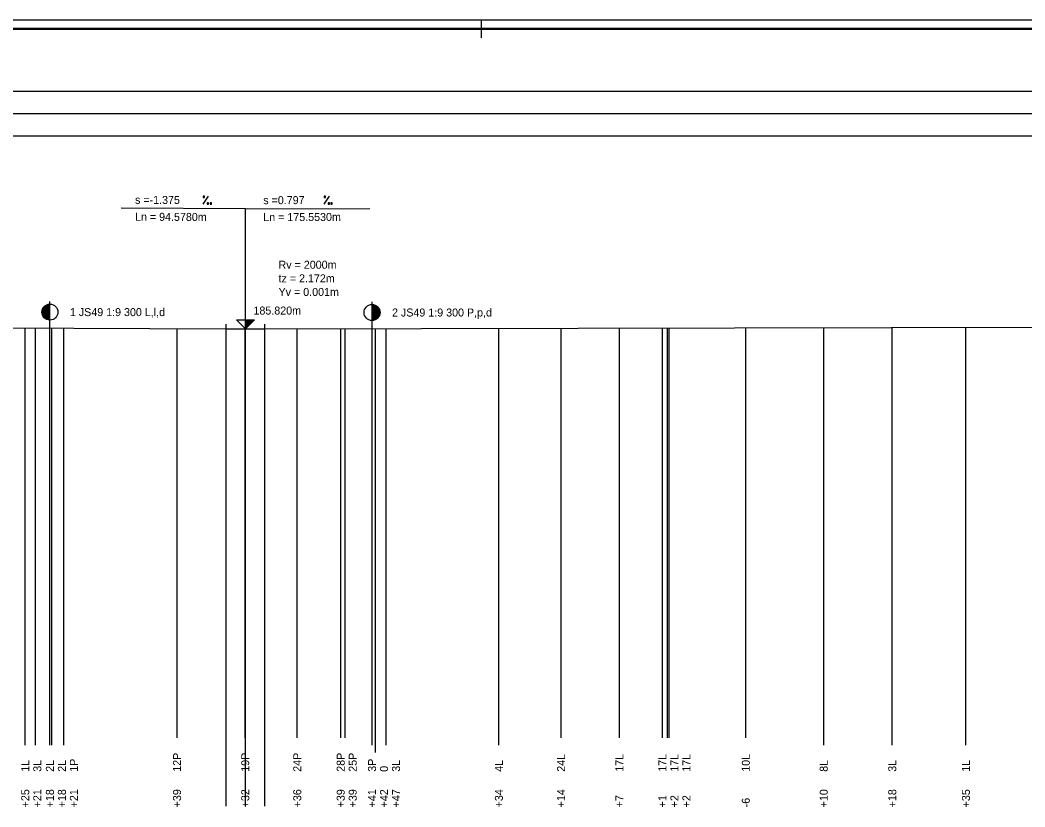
# Model space of a CAD drawing. Extents: x 0 to 10087, y -805 to 297.
# Drawn here: x 7666.2 to 7892.2, y 120.1 to 297 of the extents above; entities that cross this region are included whole.
import ezdxf

# ---------------------------------------------------------------- set-up
doc = ezdxf.new("R2010")
doc.units = 0
for name, color, linetype in [('CARA_S_OBJEKTY', 7, 'Continuous'), ('CARKY_HODNOT', 7, 'Continuous'), ('NIVELETA_CARA', 7, 'Continuous'), ('NIVELETA_TEXT', 7, 'Continuous'), ('OBJEKTY_TEXT', 7, 'Continuous'), ('RAM', 7, 'Continuous'), ('TEXT', 7, 'Continuous')]:
    doc.layers.add(name, color=color, linetype=linetype)

msp = doc.modelspace()

# ---------------------------------------------------------------- linework, layer by layer
at = {"layer": 'CARKY_HODNOT'}
for p, q in [((7667.33, 138.35), (7667.33, 227.77)), ((7669.61, 138.35), (7669.61, 227.76)), ((7672.87, 138.35), (7672.87, 227.75)), ((7673.27, 138.35), (7673.27, 227.75)), ((7676.04, 138.35), (7676.04, 227.74)), ((7701.47, 138.35), (7701.47, 227.65)), ((7712.52, 138.35), (7712.52, 227.61)), ((7716.82, 138.35), (7716.82, 227.61)), ((7716.87, 138.35), (7716.87, 227.61)), ((7721.21, 138.35), (7721.21, 227.61)), ((7728.52, 138.35), (7728.52, 227.62)), ((7738.3, 138.35), (7738.3, 227.64)), ((7739.33, 138.35), (7739.33, 227.64)), ((7745.34, 138.35), (7745.34, 227.66)), ((7746.1, 138.35), (7746.1, 227.66)), ((7748.5, 138.35), (7748.5, 227.66)), ((7773.88, 138.35), (7773.88, 227.71)), ((7787.88, 138.35), (7787.88, 227.74)), ((7801.01, 138.35), (7801.01, 227.77)), ((7810.68, 138.35), (7810.68, 227.79)), ((7811.8, 138.35), (7811.8, 227.79)), ((7812.16, 138.35), (7812.16, 227.79)), ((7829.44, 138.35), (7829.44, 227.82)), ((7846.97, 138.35), (7846.97, 227.86)), ((7862.39, 138.35), (7862.39, 227.89)), ((7878.97, 138.35), (7878.97, 227.92)), ((7667.33, 134), (7667.33, 138.35)), ((7669.61, 134), (7669.61, 138.35)), ((7672.87, 134), (7672.87, 138.35)), ((7673.27, 134), (7673.27, 138.35)), ((7676.04, 134), (7676.04, 138.35)), ((7701.47, 135.65), (7701.47, 138.35)), ((7712.52, 126.2), (7712.52, 138.35)), ((7716.82, 135.65), (7716.82, 138.35)), ((7716.87, 126.2), (7716.87, 138.35)), ((7721.21, 126.2), (7721.21, 138.35)), ((7728.52, 135.65), (7728.52, 138.35)), ((7738.3, 135.65), (7738.3, 138.35)), ((7739.33, 135.65), (7739.33, 138.35)), ((7745.34, 134), (7745.34, 138.35)), ((7746.1, 132.35), (7746.1, 138.35)), ((7748.5, 134), (7748.5, 138.35)), ((7773.88, 134), (7773.88, 138.35)), ((7787.88, 135.65), (7787.88, 138.35)), ((7801.01, 135.65), (7801.01, 138.35)), ((7810.68, 135.65), (7810.68, 138.35)), ((7811.8, 135.65), (7811.8, 138.35)), ((7812.16, 135.65), (7812.16, 138.35)), ((7829.44, 135.65), (7829.44, 138.35)), ((7846.97, 134), (7846.97, 138.35)), ((7862.39, 134), (7862.39, 138.35)), ((7878.97, 134), (7878.97, 138.35)), ((7712.52, 120.25), (7712.52, 126.2)), ((7716.87, 120.25), (7716.87, 126.2)), ((7721.21, 120.25), (7721.21, 126.2))]:
    msp.add_line(p, q, dxfattribs=at)
at = {"layer": 'NIVELETA_CARA'}
for p, q in [((300, 281), (8321.33, 281)), ((300, 276), (8321.33, 276)), ((300, 271), (8321.33, 271)), ((7716.87, 254.6), (7688.87, 254.7)), ((7716.87, 254.6), (7744.87, 254.66)), ((7716.87, 227.6), (7716.87, 254.6)), ((7712.52, 227.61), (7712.52, 228.61)), ((7716.87, 227.6), (7714.87, 229.6)), ((7714.87, 229.6), (7718.87, 229.6)), ((7716.87, 227.6), (7716.87, 229.6)), ((7718.87, 229.6), (7716.87, 227.6)), ((7716.93, 227.67), (7716.93, 229.6)), ((7717, 227.73), (7717, 229.6)), ((7717.07, 227.8), (7717.07, 229.6)), ((7717.13, 227.87), (7717.13, 229.6)), ((7717.2, 227.93), (7717.2, 229.6)), ((7717.27, 228), (7717.27, 229.6)), ((7717.33, 228.07), (7717.33, 229.6)), ((7717.4, 228.13), (7717.4, 229.6)), ((7717.47, 228.2), (7717.47, 229.6)), ((7717.53, 228.27), (7717.53, 229.6)), ((7717.6, 228.33), (7717.6, 229.6)), ((7717.67, 228.4), (7717.67, 229.6)), ((7717.73, 228.47), (7717.73, 229.6)), ((7717.8, 228.53), (7717.8, 229.6)), ((7717.87, 228.6), (7717.87, 229.6)), ((7717.93, 228.67), (7717.93, 229.6)), ((7718, 228.73), (7718, 229.6)), ((7718.07, 228.8), (7718.07, 229.6)), ((7718.13, 228.87), (7718.13, 229.6)), ((7718.2, 228.93), (7718.2, 229.6)), ((7718.27, 229), (7718.27, 229.6)), ((7718.33, 229.07), (7718.33, 229.6)), ((7718.4, 229.13), (7718.4, 229.6)), ((7718.47, 229.2), (7718.47, 229.6)), ((7718.53, 229.27), (7718.53, 229.6)), ((7718.6, 229.33), (7718.6, 229.6)), ((7718.67, 229.4), (7718.67, 229.6)), ((7718.73, 229.47), (7718.73, 229.6)), ((7718.8, 229.53), (7718.8, 229.6)), ((7721.21, 227.61), (7721.21, 228.61)), ((7532.94, 228.23), (7712.52, 227.61)), ((7712.52, 227.61), (7716.87, 227.6)), ((7712.52, 227.61), (7713.02, 227.61)), ((7713.02, 227.61), (7713.52, 227.61)), ((7713.52, 227.61), (7714.02, 227.61)), ((7714.02, 227.61), (7714.07, 227.61)), ((7716.87, 227.6), (7721.21, 227.61)), ((7719.67, 227.61), (7720.17, 227.61)), ((7720.17, 227.61), (7720.67, 227.61)), ((7720.67, 227.61), (7721.17, 227.61)), ((7721.17, 227.61), (7721.21, 227.61)), ((7721.21, 227.61), (8065.75, 228.3))]:
    msp.add_line(p, q, dxfattribs=at)
at = {"layer": 'NIVELETA_TEXT'}
for p, q in [((7707.37, 255.64), (7708.56, 257.43)), ((7707.37, 257.43), (7707.37, 257.13)), ((7707.38, 257.43), (7707.37, 257.42)), ((7707.37, 257.13), (7707.67, 257.13)), ((7707.67, 257.43), (7707.38, 257.43)), ((7707.67, 257.13), (7707.67, 257.43)), ((7708.28, 255.93), (7708.28, 255.63)), ((7708.58, 255.93), (7708.28, 255.93)), ((7708.28, 255.93), (7708.28, 255.92)), ((7708.28, 255.63), (7708.57, 255.63)), ((7708.57, 255.63), (7708.58, 255.93)), ((7708.89, 255.93), (7708.89, 255.63)), ((7708.9, 255.93), (7708.89, 255.92)), ((7708.89, 255.63), (7709.19, 255.63)), ((7709.19, 255.93), (7708.9, 255.93)), ((7709.19, 255.63), (7709.19, 255.93)), ((7734.56, 257.43), (7734.57, 257.13)), ((7734.57, 257.43), (7734.56, 257.43)), ((7734.57, 255.64), (7735.75, 257.43)), ((7734.86, 257.43), (7734.57, 257.43)), ((7734.57, 257.13), (7734.86, 257.14)), ((7734.86, 257.14), (7734.86, 257.43)), ((7735.48, 255.94), (7735.48, 255.64)), ((7735.77, 255.94), (7735.48, 255.94)), ((7735.48, 255.94), (7735.48, 255.93)), ((7735.48, 255.64), (7735.77, 255.64)), ((7735.77, 255.64), (7735.77, 255.94)), ((7736.09, 255.94), (7736.09, 255.64)), ((7736.1, 255.94), (7736.09, 255.93)), ((7736.09, 255.64), (7736.39, 255.64)), ((7736.39, 255.94), (7736.1, 255.94)), ((7736.39, 255.64), (7736.39, 255.94))]:
    msp.add_line(p, q, dxfattribs=at)
at = {"layer": 'OBJEKTY_TEXT'}
for p, q in [((7671.97, 229.79), (7671.97, 232.91)), ((7672.07, 229.74), (7672.07, 232.96)), ((7672.17, 229.69), (7672.17, 233.01)), ((7672.27, 229.65), (7672.27, 233.05)), ((7672.37, 229.62), (7672.37, 233.08)), ((7672.47, 229.6), (7672.47, 233.11)), ((7672.57, 229.58), (7672.57, 233.13)), ((7672.67, 229.56), (7672.67, 233.14)), ((7672.77, 229.55), (7672.77, 233.15)), ((7672.87, 227.75), (7672.87, 233.75)), ((7745.34, 227.66), (7745.34, 233.66)), ((7745.44, 229.46), (7745.44, 233.05)), ((7745.54, 229.47), (7745.54, 233.05)), ((7745.64, 229.48), (7745.64, 233.03)), ((7745.74, 229.5), (7745.74, 233.01)), ((7745.84, 229.53), (7745.84, 232.99)), ((7745.94, 229.56), (7745.94, 232.95)), ((7746.04, 229.6), (7746.04, 232.92)), ((7746.14, 229.64), (7746.14, 232.87)), ((7671.17, 230.76), (7671.17, 231.94)), ((7671.27, 230.53), (7671.27, 232.18)), ((7671.37, 230.36), (7671.37, 232.35)), ((7671.47, 230.22), (7671.47, 232.48)), ((7671.57, 230.11), (7671.57, 232.6)), ((7671.67, 230.01), (7671.67, 232.69)), ((7671.77, 229.93), (7671.77, 232.78)), ((7671.87, 229.85), (7671.87, 232.85)), ((7746.24, 229.7), (7746.24, 232.82)), ((7746.34, 229.76), (7746.34, 232.75)), ((7746.44, 229.83), (7746.44, 232.68)), ((7746.54, 229.92), (7746.54, 232.6)), ((7746.64, 230.01), (7746.64, 232.5)), ((7746.74, 230.13), (7746.74, 232.39)), ((7746.84, 230.26), (7746.84, 232.25)), ((7746.94, 230.43), (7746.94, 232.08)), ((7747.04, 230.67), (7747.04, 231.85))]:
    msp.add_line(p, q, dxfattribs=at)
for centre in [(7672.87, 231.35), (7745.34, 231.26)]:
    msp.add_circle(centre, 1.8, dxfattribs=at)
at = {"layer": 'RAM'}
for p, q in [((8636.33, 297), (0, 297)), ((7770, 293), (7770, 297)), ((8634.33, 295.1), (2, 295.1)), ((8634.33, 295), (2, 295)), ((8634.33, 294.9), (2, 294.9))]:
    msp.add_line(p, q, dxfattribs=at)

# ---------------------------------------------------------------- texts
at = {"layer": 'CARA_S_OBJEKTY'}
for s, p in [('1 JS49 1:9 300 L,l,d', (7677.37, 230.45)), ('2 JS49 1:9 300 P,p,d', (7749.84, 230.36))]:
    msp.add_text(s, height=1.8, dxfattribs=at).set_placement(p)
at = {"layer": 'NIVELETA_TEXT'}
for s, rotation, p in [('s =-1.375', 359.8031, (7692.02, 255.69)), ('s =0.797', 0.1142, (7720.87, 255.61)), ('Ln = 94.5780m', 359.8031, (7692.02, 251.89)), ('Ln = 175.5530m', 0.1142, (7720.87, 251.81))]:
    msp.add_text(s, height=1.8, rotation=rotation, dxfattribs=at).set_placement(p)
for s, p in [('Rv = 2000m', (7724.31, 241.1)), ('tz = 2.172m', (7724.31, 238.04)), ('Yv = 0.001m', (7724.31, 234.98)), ('185.820m', (7718.67, 230.8))]:
    msp.add_text(s, height=1.8, dxfattribs=at).set_placement(p)
at = {"layer": 'TEXT'}
for s, p in [('12P', (7702.37, 128)), ('19P', (7717.72, 128)), ('24P', (7729.42, 128)), ('28P', (7739.2, 128)), ('25P', (7741.9, 128)), ('24L', (7788.78, 128)), ('17L', (7801.91, 128)), ('17L', (7811.58, 128)), ('17L', (7814.28, 128)), ('17L', (7816.98, 128)), ('10L', (7830.34, 128)), ('1L', (7668.23, 128)), ('3L', (7670.93, 128)), ('2L', (7673.77, 128)), ('2L', (7676.47, 128)), ('1P', (7679.17, 128)), ('3P', (7746.24, 128)), ('0', (7748.94, 128)), ('3L', (7751.64, 128)), ('4L', (7774.78, 128)), ('8L', (7847.87, 128)), ('3L', (7863.29, 128)), ('1L', (7879.87, 128)), ('+25', (7668.23, 120)), ('+21', (7670.93, 120)), ('+18', (7673.77, 120)), ('+18', (7676.47, 120)), ('+21', (7679.17, 120)), ('+39', (7702.37, 120)), ('+32', (7717.72, 120)), ('+36', (7729.42, 120)), ('+39', (7739.2, 120)), ('+39', (7741.9, 120)), ('+41', (7746.24, 120)), ('+42', (7748.94, 120)), ('+47', (7751.64, 120)), ('+34', (7774.78, 120)), ('+14', (7788.78, 120)), ('+7', (7801.91, 120)), ('+1', (7811.58, 120)), ('+2', (7814.28, 120)), ('+2', (7816.98, 120)), ('+10', (7847.87, 120)), ('+18', (7863.29, 120)), ('+35', (7879.87, 120)), ('-6', (7830.34, 120))]:
    msp.add_text(s, height=1.8, rotation=90, dxfattribs=at).set_placement(p)

doc.saveas('drawing.dxf')
